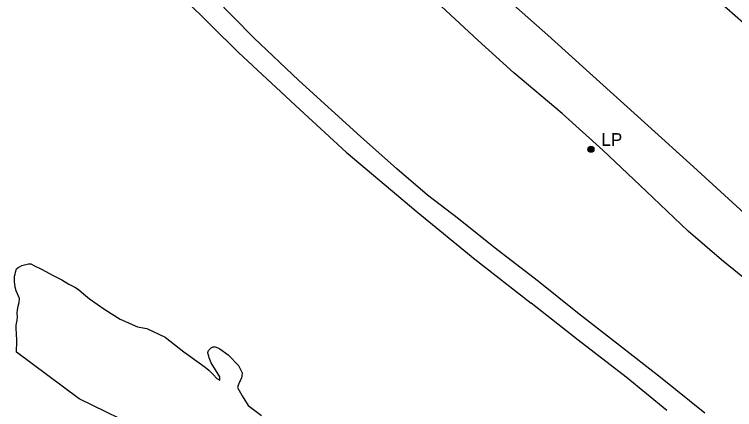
# Model space of a CAD drawing. Extents: x 368532 to 392481, y 10654822 to 10676899.
# Drawn here: x 380394.7 to 380676.6, y 10658434.2 to 10658588.9 of the extents above; entities that cross this region are included whole.
import ezdxf

# ---------------------------------------------------------------- set-up
doc = ezdxf.new("R2010")
doc.units = 0
for name, color, linetype in [('p_dtm obscured area', 7, 'Continuous'), ('p_road dirt road', 7, 'Continuous'), ('p_structure wall', 7, 'Continuous'), ('p_utility general pole', 7, 'Continuous')]:
    doc.layers.add(name, color=color, linetype=linetype)

msp = doc.modelspace()

# ---------------------------------------------------------------- linework, layer by layer
at = {"layer": 'p_dtm obscured area'}
msp.add_lwpolyline([(380472.57, 10658412.94), (380420.12, 10658438.47), (380395.56, 10658456.71), (380395.71, 10658461.16), (380395.57, 10658464.14), (380395.45, 10658465.75), (380395.44, 10658467.3), (380395.86, 10658469.18), (380395.91, 10658470.58), (380395.86, 10658471.99), (380396, 10658473.31), (380396.26, 10658474.76), (380396.64, 10658476.17), (380396.67, 10658477.7), (380396, 10658479.5), (380395.46, 10658480.73), (380395.02, 10658482.07), (380394.73, 10658484.41), (380394.77, 10658486.46), (380395, 10658487.18), (380395.16, 10658488.06), (380395.6, 10658489.31), (380396.18, 10658489.84), (380396.72, 10658490.15), (380397.66, 10658490.64), (380398.7, 10658490.9), (380400.26, 10658491.31), (380401.15, 10658491.31), (380402.66, 10658490.46), (380405.29, 10658489.11), (380409.96, 10658486.68), (380413.36, 10658484.94), (380416.07, 10658483.36), (380418.33, 10658482.11), (380419.76, 10658481.21), (380421.74, 10658479.5), (380424.16, 10658477.52), (380430.06, 10658473.34), (380436.16, 10658469.56), (380442.89, 10658466.63), (380446.58, 10658465.91), (380453.68, 10658462.53), (380461.01, 10658456.87), (380467.04, 10658452.46), (380469.37, 10658450.78), (380470.86, 10658449.62), (380472.46, 10658447.96), (380473.98, 10658446.42), (380475.17, 10658445.68), (380475.13, 10658446.99), (380471.79, 10658452.55), (380470.97, 10658454.52), (380470.79, 10658455.14), (380470.52, 10658455.91), (380470.38, 10658456.63), (380470.66, 10658457.32), (380471.29, 10658457.94), (380471.78, 10658458.37), (380472.5, 10658458.77), (380473.27, 10658458.82), (380474.33, 10658458.35), (380475.08, 10658458.03), (380478.44, 10658455.66), (380482.49, 10658451.47), (380483.82, 10658448.63), (380483.77, 10658447.3), (380483.62, 10658446.6), (380483.2, 10658445.77), (380482.86, 10658445.06), (380482.41, 10658444), (380482.08, 10658442.91), (380483.9, 10658439.65), (380486.26, 10658435.79), (380491.48, 10658431.91)], dxfattribs=at)
at = {"layer": 'p_road dirt road'}
for p, q in [((380576.3, 10658578.64), (380544.31, 10658608.37)), ((380488.43, 10658579.72), (380471.7, 10658596.75)), ((380585.03, 10658597.18), (380603.44, 10658580.71)), ((380461.08, 10658595.18), (380482.41, 10658574.01)), ((380505.99, 10658563.03), (380488.43, 10658579.72)), ((380590.2, 10658566.03), (380576.3, 10658578.64)), ((380603.44, 10658580.71), (380623.81, 10658562.36)), ((380482.41, 10658574.01), (380506.41, 10658551.62)), ((380609.05, 10658550.03), (380590.2, 10658566.03)), ((380530.16, 10658541.12), (380505.99, 10658563.03)), ((380623.81, 10658562.36), (380642.61, 10658545.41)), ((380506.41, 10658551.62), (380524.54, 10658535)), ((380625.06, 10658535.76), (380609.05, 10658550.03)), ((380642.61, 10658545.41), (380660.5, 10658529.26)), ((380544.46, 10658528.49), (380530.16, 10658541.12)), ((380524.54, 10658535), (380552.64, 10658511.35)), ((380641.96, 10658519.66), (380625.06, 10658535.76)), ((380556.4, 10658518.16), (380544.46, 10658528.49)), ((380660.5, 10658529.26), (380681.76, 10658509.75)), ((380658.43, 10658504.05), (380641.96, 10658519.66)), ((380568.51, 10658508.82), (380556.4, 10658518.16)), ((380552.64, 10658511.35), (380574.94, 10658493.05)), ((380582.34, 10658497.78), (380568.51, 10658508.82)), ((380671.45, 10658492.77), (380658.43, 10658504.05)), ((380599.82, 10658484.31), (380582.34, 10658497.78)), ((380574.94, 10658493.05), (380597.04, 10658475.89)), ((380683.2, 10658483.25), (380671.45, 10658492.77)), ((380615.09, 10658472.05), (380599.82, 10658484.31)), ((380615.35, 10658461.37), (380597.04, 10658475.89)), ((380631.53, 10658459.27), (380615.09, 10658472.05)), ((380634.11, 10658446.86), (380615.35, 10658461.37)), ((380647.58, 10658446.78), (380631.53, 10658459.27)), ((380650.04, 10658433.88), (380634.11, 10658446.86)), ((380665, 10658432.87), (380647.58, 10658446.78))]:
    msp.add_line(p, q, dxfattribs=at)
at = {"layer": 'p_structure wall'}
msp.add_line((380670.26, 10658594.19), (380708.27, 10658560.55), dxfattribs=at)
at = {"layer": 'p_utility general pole'}
for radius in [1.19, 0.901, 0.608, 0.337, 0.12]:
    msp.add_circle((380620.35, 10658536.11), radius, dxfattribs=at)

# ---------------------------------------------------------------- texts
msp.add_text('LP', height=5, dxfattribs=at).set_placement((380624.47, 10658537.4))

doc.saveas('drawing.dxf')
